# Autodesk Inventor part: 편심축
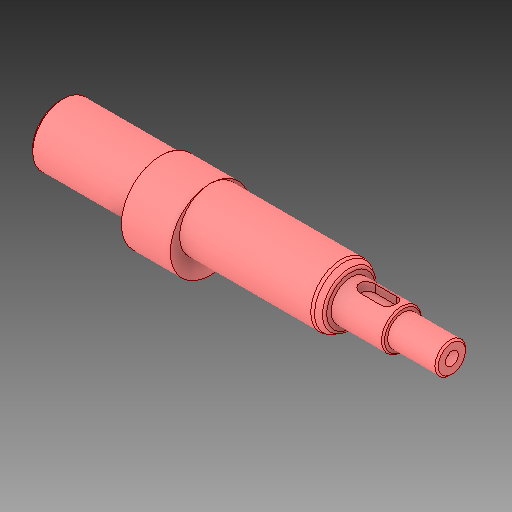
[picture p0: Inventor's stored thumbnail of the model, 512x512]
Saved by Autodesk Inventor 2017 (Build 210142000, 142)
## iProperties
Created: 2024-08
Part Number: 편심축
Material: 일반
Document SubType Name: Modeling
Designer: MRC
Density: 1 g/cm^3
Appearance: 기본값
Author: jhkim
Sending System: Autodesk Inventor 2025
Preprocessor: ST-DEVELOPER v20
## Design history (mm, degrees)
feature "솔리드1"
node "솔리드2"
